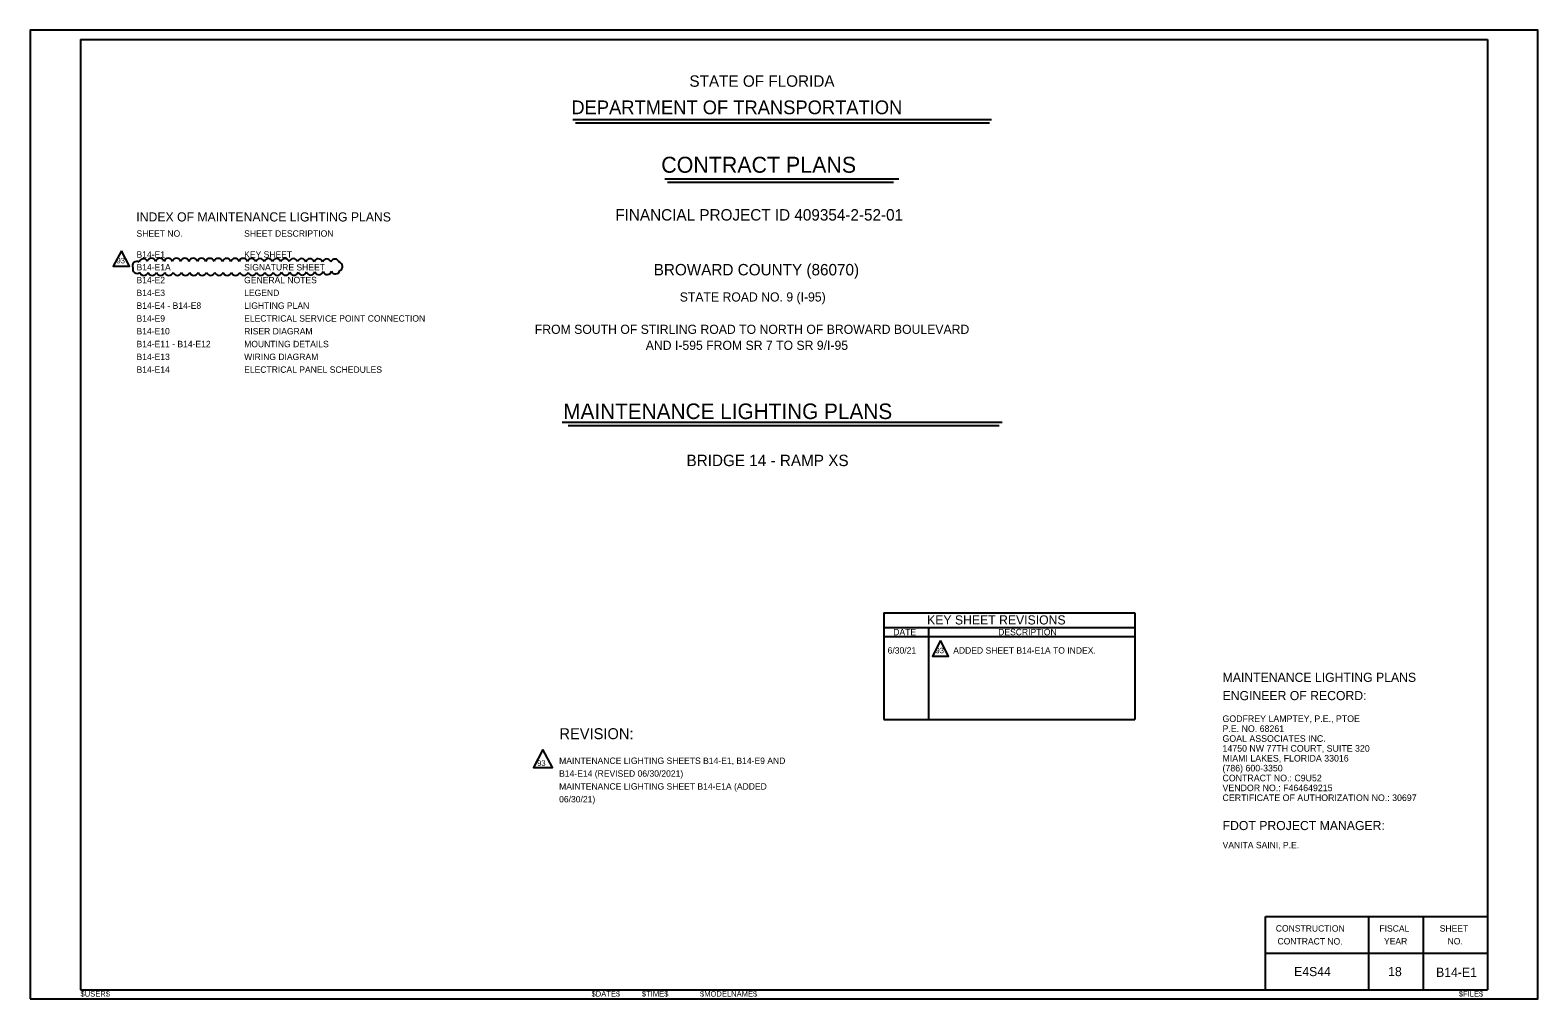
# Model space of a CAD drawing. Extents: x -828 to -804, y -2199 to -1895.
import ezdxf

# ---------------------------------------------------------------- set-up
doc = ezdxf.new("R2010")
doc.units = 0
for name, color, linetype in [('ActivePointCell_dp', 7, 'Continuous'), ('AdhocPoint_dp', 7, 'Continuous'), ('Cloud_dp', 7, 'Continuous'), ('PlotBorder_dp', 7, 'Continuous'), ('SheetBorder_dp', 7, 'Continuous'), ('SheetLines_dp', 7, 'Continuous'), ('SumBoxLines_dp', 7, 'Continuous'), ('TextLabel', 7, 'Continuous'), ('TextMinor', 7, 'Continuous'), ('TextNotes', 7, 'Continuous'), ('TextTitle', 7, 'Continuous')]:
    doc.layers.add(name, color=color, linetype=linetype)

msp = doc.modelspace()

# ---------------------------------------------------------------- linework, layer by layer
at = {"layer": 'ActivePointCell_dp'}
msp.add_line((-804.277, -2188.624), (-804.277, -2188.624), dxfattribs=at)
at = {"layer": 'AdhocPoint_dp'}
msp.add_line((-820.227, -2199.124), (-820.227, -2199.124), dxfattribs=at)
at = {"layer": 'Cloud_dp'}
for points in [[(-819.229, -2190.937), (-819.317, -2191.106), (-819.141, -2191.106)], [(-810.265, -2195.203), (-810.353, -2195.372), (-810.177, -2195.372)]]:
    msp.add_lwpolyline(points, close=True, dxfattribs=at)
for centre, radius, start, end in [((-818.988, -2191.072), 0.0478, 23.1041, 168.1041), ((-818.899, -2191.067), 0.0478, 17.3932, 162.3932), ((-818.808, -2191.068), 0.0478, 17.3932, 162.3932), ((-818.716, -2191.068), 0.0478, 17.3932, 162.3932), ((-818.625, -2191.068), 0.0478, 17.3932, 162.3932), ((-818.534, -2191.068), 0.0478, 17.3932, 162.3932), ((-818.443, -2191.068), 0.0478, 17.3932, 162.3932), ((-818.351, -2191.068), 0.0478, 17.3932, 162.3932), ((-818.26, -2191.069), 0.0478, 17.3932, 162.3932), ((-818.169, -2191.069), 0.0478, 17.3932, 162.3932), ((-818.077, -2191.069), 0.0478, 17.3932, 162.3932), ((-817.986, -2191.069), 0.0478, 17.3931, 162.3931), ((-817.895, -2191.069), 0.0478, 17.3856, 162.3856), ((-817.804, -2191.07), 0.0478, 17.3699, 162.3699), ((-817.712, -2191.07), 0.0478, 17.3517, 162.3517), ((-817.621, -2191.07), 0.0478, 17.3304, 162.3304), ((-817.53, -2191.07), 0.0478, 17.3049, 162.3049), ((-817.439, -2191.071), 0.0478, 17.2737, 162.2737), ((-817.347, -2191.071), 0.0478, 17.2341, 162.2341), ((-817.256, -2191.071), 0.0478, 17.1817, 162.1817), ((-817.165, -2191.072), 0.0478, 17.1076, 162.1076), ((-817.074, -2191.073), 0.0478, 16.9905, 161.9905), ((-816.983, -2191.074), 0.0478, 16.7593, 161.7593), ((-816.892, -2191.076), 0.0479, 15.0311, 160.0311), ((-819.06, -2191.103), 0.0478, 59.3679, 204.3679), ((-819.057, -2191.137), 0.0478, 162.9173, 307.9173), ((-818.982, -2191.16), 0.0478, 197.5, 342.5), ((-818.891, -2191.16), 0.0478, 197.5, 342.5), ((-818.8, -2191.16), 0.0478, 197.5, 342.5), ((-818.709, -2191.16), 0.0478, 197.5, 342.5), ((-818.617, -2191.16), 0.0478, 197.5, 342.5), ((-818.526, -2191.16), 0.0478, 197.5, 342.5), ((-818.435, -2191.16), 0.0478, 197.5, 342.5), ((-818.344, -2191.16), 0.0478, 197.5, 342.5), ((-818.252, -2191.16), 0.0478, 197.5, 342.5), ((-818.161, -2191.16), 0.0478, 197.5, 342.5), ((-818.07, -2191.16), 0.0478, 197.5, 342.5), ((-817.979, -2191.16), 0.0478, 197.5, 342.5), ((-817.887, -2191.16), 0.0478, 197.5208, 342.5208), ((-817.796, -2191.16), 0.0478, 197.584, 342.584), ((-817.705, -2191.16), 0.0478, 197.6576, 342.6576), ((-817.614, -2191.16), 0.0478, 197.7436, 342.7436), ((-817.522, -2191.159), 0.0478, 197.8459, 342.8459), ((-817.431, -2191.158), 0.0478, 197.9703, 342.9703), ((-817.34, -2191.158), 0.0478, 198.1263, 343.1263), ((-817.249, -2191.156), 0.0478, 198.3299, 343.3299), ((-817.158, -2191.155), 0.0478, 198.6118, 343.6118), ((-817.066, -2191.153), 0.0478, 199.0404, 344.0404), ((-816.975, -2191.15), 0.0478, 199.8179, 344.8179), ((-816.885, -2191.144), 0.0478, 202.212, 347.212), ((-816.856, -2191.11), 0.0478, 292.0417, 77.0417)]:
    msp.add_arc(centre, radius, start, end, dxfattribs=at)
at = {"layer": 'PlotBorder_dp'}
msp.add_lwpolyline([(-820.227, -2199.124), (-803.727, -2199.124), (-803.727, -2188.524), (-820.227, -2188.524)], close=True, dxfattribs=at)
at = {"layer": 'SheetBorder_dp'}
for p, q in [((-819.677, -2188.624), (-819.677, -2199.024)), ((-819.677, -2188.624), (-804.277, -2188.624)), ((-804.277, -2188.624), (-804.277, -2199.024)), ((-819.677, -2199.024), (-804.277, -2199.024))]:
    msp.add_line(p, q, dxfattribs=at)
at = {"layer": 'SheetLines_dp'}
for p, q in [((-806.708, -2198.224), (-804.277, -2198.224)), ((-806.708, -2199.024), (-806.708, -2198.224)), ((-805.577, -2199.024), (-805.577, -2198.224)), ((-804.977, -2199.024), (-804.977, -2198.224)), ((-806.708, -2198.624), (-804.277, -2198.624))]:
    msp.add_line(p, q, dxfattribs=at)
at = {"layer": 'SumBoxLines_dp'}
for p, q in [((-810.885, -2194.9), (-810.885, -2196.068)), ((-810.885, -2194.9), (-808.138, -2194.9)), ((-808.138, -2194.9), (-808.138, -2196.068)), ((-810.885, -2195.06), (-808.138, -2195.06)), ((-810.885, -2195.16), (-808.138, -2195.16)), ((-810.395, -2195.06), (-810.395, -2196.068)), ((-810.885, -2196.068), (-808.138, -2196.068))]:
    msp.add_line(p, q, dxfattribs=at)
at = {"layer": 'TextNotes'}
msp.add_lwpolyline([(-814.615, -2196.395), (-814.717, -2196.593), (-814.512, -2196.593)], close=True, dxfattribs=at)
at = {"layer": 'TextTitle'}
for p, q in [((-814.289, -2189.5), (-809.707, -2189.5)), ((-814.257, -2189.538), (-809.729, -2189.538)), ((-813.281, -2190.15), (-810.719, -2190.15)), ((-813.253, -2190.188), (-810.777, -2190.188)), ((-814.404, -2192.813), (-809.59, -2192.813)), ((-814.339, -2192.851), (-809.624, -2192.851))]:
    msp.add_line(p, q, dxfattribs=at)

# ---------------------------------------------------------------- texts
at = {"layer": 'Cloud_dp'}
for p in [(-819.282, -2191.076), (-810.319, -2195.342)]:
    msp.add_text('93', height=0.06, rotation=0, dxfattribs=at).set_placement(p)
at = {"layer": 'TextLabel'}
for s, height, p in [('INDEX OF MAINTENANCE LIGHTING PLANS', 0.1, (-819.065, -2190.617)), ('FINANCIAL PROJECT ID 409354-2-52-01', 0.125, (-813.823, -2190.607)), ('B14-E1', 0.07, (-819.063, -2191.013)), ('KEY SHEET', 0.07, (-817.885, -2191.013)), ('B14-E1A', 0.07, (-819.063, -2191.153)), ('SIGNATURE SHEET', 0.07, (-817.885, -2191.153)), ('BROWARD COUNTY (86070)', 0.125, (-813.403, -2191.207)), ('B14-E2', 0.07, (-819.063, -2191.293)), ('B14-E3', 0.07, (-819.063, -2191.433)), ('GENERAL NOTES', 0.07, (-817.885, -2191.293)), ('LEGEND', 0.07, (-817.885, -2191.433)), ('B14-E4 - B14-E8', 0.07, (-819.063, -2191.573)), ('LIGHTING PLAN', 0.07, (-817.885, -2191.573)), ('STATE ROAD NO. 9 (I-95)', 0.1, (-813.118, -2191.493)), ('B14-E9', 0.07, (-819.063, -2191.713)), ('ELECTRICAL SERVICE POINT CONNECTION', 0.07, (-817.885, -2191.713)), ('B14-E10', 0.07, (-819.063, -2191.853)), ('RISER DIAGRAM', 0.07, (-817.885, -2191.853)), ('FROM SOUTH OF STIRLING ROAD TO NORTH OF BROWARD BOULEVARD', 0.1, (-814.704, -2191.847)), ('B14-E11 - B14-E12', 0.07, (-819.063, -2191.993)), ('MOUNTING DETAILS', 0.07, (-817.885, -2191.993)), ('AND I-595 FROM SR 7 TO SR 9/I-95', 0.1, (-813.49, -2192.022)), ('B14-E13', 0.07, (-819.063, -2192.133)), ('WIRING DIAGRAM', 0.07, (-817.885, -2192.133)), ('B14-E14', 0.07, (-819.063, -2192.273)), ('ELECTRICAL PANEL SCHEDULES', 0.07, (-817.885, -2192.273)), ('BRIDGE 14 - RAMP XS', 0.125, (-813.044, -2193.294)), ('KEY SHEET REVISIONS', 0.1, (-810.411, -2195.027)), ('MAINTENANCE LIGHTING PLANS', 0.1, (-807.177, -2195.655)), ('ENGINEER OF RECORD:', 0.1, (-807.177, -2195.855)), ('GODFREY LAMPTEY, P.E., PTOE', 0.07202, (-807.178, -2196.094)), ('P.E. NO. 68261', 0.07202, (-807.178, -2196.203)), ('REVISION:', 0.12, (-814.435, -2196.282)), ('GOAL ASSOCIATES INC. ', 0.07202, (-807.178, -2196.311)), ('14750 NW 77TH COURT, SUITE 320', 0.07202, (-807.178, -2196.419)), ('MIAMI LAKES, FLORIDA 33016', 0.07202, (-807.178, -2196.527)), ('(786) 600-3350', 0.07202, (-807.178, -2196.635)), ('VENDOR NO.: F464649215', 0.07202, (-807.178, -2196.851)), ('CONTRACT NO.: C9U52', 0.07202, (-807.178, -2196.743)), ('CERTIFICATE OF AUTHORIZATION NO.: 30697', 0.07202, (-807.178, -2196.959)), ('E4S44', 0.1, (-806.394, -2198.875)), ('18', 0.1, (-805.365, -2198.875)), ('B14-E1', 0.1, (-804.84, -2198.883))]:
    msp.add_text(s, height=height, dxfattribs=at).set_placement(p)
at = {"layer": 'TextMinor'}
for s, height, p in [('6/30/21', 0.07, (-810.843, -2195.346)), ('ADDED SHEET B14-E1A TO INDEX.', 0.07, (-810.125, -2195.346)), ('$FILE$', 0.06, (-804.592, -2199.099))]:
    msp.add_text(s, height=height, dxfattribs=at).set_placement(p)
for s, p in [('$USER$', (-819.676, -2199.099)), ('$DATE$', (-814.083, -2199.099)), ('$TIME$', (-813.532, -2199.099)), ('$MODELNAME$', (-812.896, -2199.099))]:
    msp.add_text(s, height=0.06, rotation=360, dxfattribs=at).set_placement(p)
at = {"layer": 'TextNotes'}
for s, height, p in [('SHEET NO.', 0.07, (-819.063, -2190.784)), ('SHEET DESCRIPTION', 0.07, (-817.885, -2190.784)), ('DATE', 0.07, (-810.781, -2195.145)), ('DESCRIPTION', 0.07, (-809.633, -2195.145)), ('MAINTENANCE LIGHTING SHEETS B14-E1, B14-E9 AND ', 0.07, (-814.438, -2196.553)), ('B14-E14 (REVISED 06/30/2021)', 0.07, (-814.438, -2196.693)), ('MAINTENANCE LIGHTING SHEET B14-E1A (ADDED ', 0.07, (-814.438, -2196.834)), ('06/30/21)', 0.07, (-814.438, -2196.974)), ('FDOT PROJECT MANAGER:', 0.1, (-807.177, -2197.277)), ('VANITA SAINI, P.E.', 0.07, (-807.177, -2197.476))]:
    msp.add_text(s, height=height, dxfattribs=at).set_placement(p)
for s, height, rotation, p in [('93', 0.0622, 0, (-814.679, -2196.575)), ('CONSTRUCTION', 0.07, 359.8607, (-806.595, -2198.387)), ('CONTRACT NO.', 0.07, 359.8607, (-806.576, -2198.528)), ('FISCAL', 0.07, 359.8607, (-805.461, -2198.388)), ('YEAR', 0.07, 359.8607, (-805.411, -2198.528)), ('SHEET', 0.07, 359.8607, (-804.801, -2198.388)), ('NO.', 0.07, 359.8607, (-804.715, -2198.528))]:
    msp.add_text(s, height=height, rotation=rotation, dxfattribs=at).set_placement(p)
at = {"layer": 'TextTitle'}
for s, height, p in [('STATE OF FLORIDA', 0.125, (-813.012, -2189.143)), ('DEPARTMENT OF TRANSPORTATION', 0.15, (-814.304, -2189.443)), ('CONTRACT PLANS', 0.175, (-813.32, -2190.084)), ('MAINTENANCE LIGHTING PLANS', 0.17, (-814.393, -2192.779))]:
    msp.add_text(s, height=height, dxfattribs=at).set_placement(p)

doc.saveas('drawing.dxf')
